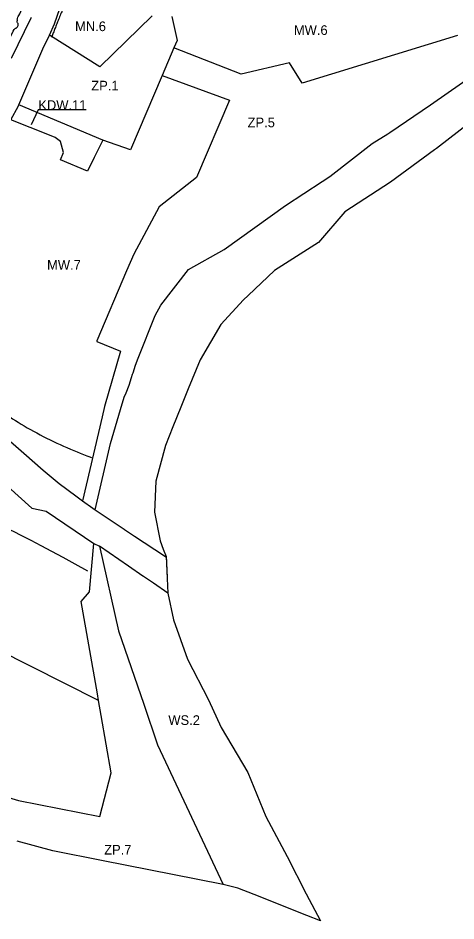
# Model space of a CAD drawing. Extents: x 7424788 to 7425732, y 5549810 to 5550591.
# Drawn here: x 7425235.6 to 7425416.8, y 5549810.3 to 5550184.4 of the extents above; entities that cross this region are included whole.
import ezdxf

# ---------------------------------------------------------------- set-up
doc = ezdxf.new("R2010")
doc.units = 0
for name, color, linetype in [('WIL_granica obszaru objętego planem', 7, 'Continuous'), ('WIL_linia rozgraniczające tereny o różnym przeznaczeniu lub różnych zasadach zagospodarowania', 7, 'Continuous'), ('WIL_linia rozgraniczające tereny o różnym przeznaczeniu lub różnych zasadach zagospodarowania_OPISY', 7, 'Continuous'), ('WIL_nieprzekraczalne linie zabudowy', 7, 'Continuous')]:
    doc.layers.add(name, color=color, linetype=linetype)

msp = doc.modelspace()

# ---------------------------------------------------------------- linework, layer by layer
at = {"layer": 'WIL_granica obszaru objętego planem'}
for p, q in [((7425407.96, 5550129.83), (7425389.71, 5550116.43)), ((7425360, 5550091.47), (7425341.78, 5550079.86)), ((7425341.78, 5550079.86), (7425330.79, 5550069.41)), ((7425294.44, 5549967.79), (7425295.65, 5549964.3)), ((7425295.65, 5549964.3), (7425296.91, 5549961.35)), ((7425296.91, 5549961.35), (7425297.65, 5549946.19)), ((7425319.68, 5549890.47), (7425330.71, 5549871.85)), ((7425330.71, 5549871.85), (7425338.21, 5549853.65)), ((7425338.21, 5549853.65), (7425346.99, 5549836.99)), ((7425346.99, 5549836.99), (7425354.82, 5549821.59)), ((7425326.6, 5549823.95), (7425320.44, 5549825.47)), ((7425333.35, 5549821.26), (7425326.6, 5549823.95)), ((7425354.82, 5549821.59), (7425360.83, 5549810.31))]:
    msp.add_line(p, q, dxfattribs=at)
for points in [[(7425440.98, 5550153.66), (7425422.93, 5550141.34), (7425408.74, 5550130.43), (7425407.96, 5550129.83)], [(7425389.71, 5550116.43), (7425370.86, 5550104.18), (7425360, 5550091.47)], [(7425330.79, 5550069.41), (7425328.9, 5550067.62), (7425319.6, 5550057.42)], [(7425319.6, 5550057.42), (7425310.98, 5550042.77), (7425306, 5550030.84), (7425303, 5550023.25), (7425299.7, 5550015.03)], [(7425299.7, 5550015.03), (7425296.62, 5550007.38), (7425292.61, 5549992.55)], [(7425292.61, 5549992.55), (7425292.14, 5549979.67), (7425294.44, 5549967.79)], [(7425297.65, 5549946.19), (7425299.98, 5549935.11), (7425305.76, 5549918.78), (7425314.39, 5549901.91), (7425319.68, 5549890.47)], [(7425270.8, 5549835.23), (7425250.01, 5549839.34), (7425235.24, 5549843.32)], [(7425320.44, 5549825.47), (7425299.52, 5549829.56), (7425270.8, 5549835.23)], [(7425360.83, 5549810.31), (7425355.08, 5549812.58), (7425333.35, 5549821.26)]]:
    msp.add_lwpolyline(points, dxfattribs=at)
msp.add_open_spline([(7425296.93, 5549961.04), (7425297.39, 5549951.5)], degree=1, dxfattribs=at)
at = {"layer": 'WIL_linia rozgraniczające tereny o różnym przeznaczeniu lub różnych zasadach zagospodarowania'}
for p, q in [((7425250.74, 5550182.05), (7425252.87, 5550188.4)), ((7425240.93, 5550184.38), (7425232.72, 5550167.74)), ((7425241.1, 5550184.72), (7425240.93, 5550184.38)), ((7425291.09, 5550185.38), (7425269.43, 5550164.2)), ((7425299.29, 5550185.06), (7425301.41, 5550175.18)), ((7425248.65, 5550177.3), (7425250.74, 5550182.05)), ((7425247.98, 5550175.79), (7425248.65, 5550177.3)), ((7425249.1, 5550177.02), (7425248.65, 5550177.3)), ((7425269.43, 5550164.2), (7425249.1, 5550177.02)), ((7425417.42, 5550177.24), (7425353.21, 5550157.39)), ((7425245.81, 5550171.63), (7425247.21, 5550174.53)), ((7425247.21, 5550174.53), (7425247.98, 5550175.79)), ((7425301.41, 5550175.18), (7425300.08, 5550172.04)), ((7425243.33, 5550165.86), (7425245.81, 5550171.63)), ((7425300.08, 5550172.04), (7425295.22, 5550160.57)), ((7425327.95, 5550161.15), (7425300.08, 5550172.04)), ((7425235.89, 5550148.41), (7425243.33, 5550165.86)), ((7425347.9, 5550165.87), (7425327.95, 5550161.15)), ((7425353.21, 5550157.39), (7425347.9, 5550165.87)), ((7425406.34, 5550148.48), (7425432.46, 5550166.86)), ((7425295.22, 5550160.57), (7425282.2, 5550129.85)), ((7425295.22, 5550160.57), (7425323.19, 5550150.46)), ((7425323.19, 5550150.46), (7425309.45, 5550118.4)), ((7425232.57, 5550142.3), (7425235.74, 5550148.06)), ((7425235.74, 5550148.06), (7425235.89, 5550148.41)), ((7425270.67, 5550133.81), (7425235.89, 5550148.41)), ((7425389.52, 5550137.03), (7425406.34, 5550148.48)), ((7425248.67, 5550135.84), (7425232.57, 5550142.3)), ((7425250.95, 5550134.92), (7425248.67, 5550135.84)), ((7425382.11, 5550132.42), (7425388.64, 5550136.46)), ((7425388.64, 5550136.46), (7425389.52, 5550137.03)), ((7425253.18, 5550133.33), (7425250.95, 5550134.92)), ((7425254.45, 5550128.72), (7425253.18, 5550133.33)), ((7425270.67, 5550133.81), (7425267.16, 5550126.7)), ((7425282.2, 5550129.85), (7425270.67, 5550133.81)), ((7425364.7, 5550118.79), (7425382.11, 5550132.42)), ((7425253.18, 5550125.7), (7425254.45, 5550128.72)), ((7425407.96, 5550129.83), (7425389.71, 5550116.43)), ((7425264.31, 5550120.93), (7425253.18, 5550125.7)), ((7425267.16, 5550126.7), (7425264.31, 5550120.93)), ((7425309.45, 5550118.4), (7425294.07, 5550106.21)), ((7425346.27, 5550106.71), (7425361.44, 5550116.75)), ((7425361.44, 5550116.75), (7425364.7, 5550118.79)), ((7425294.07, 5550106.21), (7425283.46, 5550086.58)), ((7425320.95, 5550088.57), (7425346.27, 5550106.71)), ((7425360, 5550091.47), (7425341.78, 5550079.86)), ((7425306.1, 5550080.19), (7425320.95, 5550088.57)), ((7425283.46, 5550086.58), (7425280.53, 5550079.67)), ((7425280.53, 5550079.67), (7425268.2, 5550050.62)), ((7425294.74, 5550065.5), (7425306.1, 5550080.19)), ((7425341.78, 5550079.86), (7425330.79, 5550069.41)), ((7425292.35, 5550061.18), (7425294.74, 5550065.5)), ((7425285.33, 5550043.54), (7425292.35, 5550061.18)), ((7425268.2, 5550050.62), (7425268.27, 5550050.36)), ((7425268.27, 5550050.36), (7425278, 5550046.47)), ((7425278, 5550046.47), (7425271.32, 5550023.54)), ((7425284.16, 5550040.6), (7425285.33, 5550043.54)), ((7425283.2, 5550037.43), (7425284.16, 5550040.6)), ((7425281.66, 5550032.37), (7425282.61, 5550035.5)), ((7425282.61, 5550035.5), (7425283.03, 5550036.94)), ((7425283.03, 5550036.94), (7425283.2, 5550037.43)), ((7425280.3, 5550029.13), (7425281.66, 5550032.37)), ((7425278.01, 5550022.23), (7425279.54, 5550027.4)), ((7425279.54, 5550027.4), (7425280.3, 5550029.13)), ((7425271.32, 5550023.54), (7425270.43, 5550019.19)), ((7425273.87, 5550008.16), (7425278.01, 5550022.23)), ((7425270.43, 5550019.19), (7425262.31, 5549984.45)), ((7425231.35, 5550009.93), (7425238.05, 5550004.15)), ((7425267.57, 5549980.71), (7425273.87, 5550008.16)), ((7425216.3, 5550003.77), (7425241.29, 5549981.33)), ((7425238.05, 5550004.15), (7425246.02, 5549997.14)), ((7425246.02, 5549997.14), (7425252.63, 5549991.58)), ((7425252.63, 5549991.58), (7425259.51, 5549986.44)), ((7425259.51, 5549986.44), (7425262.31, 5549984.45)), ((7425262.31, 5549984.45), (7425266.58, 5549981.41)), ((7425241.29, 5549981.33), (7425247.29, 5549980.06)), ((7425247.29, 5549980.06), (7425266.97, 5549966.64)), ((7425266.58, 5549981.41), (7425267.57, 5549980.71)), ((7425267.57, 5549980.71), (7425279.52, 5549972.59)), ((7425279.52, 5549972.59), (7425279.66, 5549972.5)), ((7425279.66, 5549972.5), (7425283.81, 5549969.76)), ((7425283.81, 5549969.76), (7425296.24, 5549961.55)), ((7425294.44, 5549967.79), (7425295.65, 5549964.3)), ((7425265.15, 5549946.68), (7425266.97, 5549966.64)), ((7425266.97, 5549966.64), (7425269.31, 5549965.64)), ((7425269.31, 5549965.64), (7425277.22, 5549930.55)), ((7425281.27, 5549957.34), (7425269.31, 5549965.64)), ((7425295.65, 5549964.3), (7425296.91, 5549961.35)), ((7425296.24, 5549961.55), (7425296.92, 5549961.07)), ((7425296.91, 5549961.35), (7425296.92, 5549961.07)), ((7425296.91, 5549961.35), (7425297.65, 5549946.19)), ((7425287.25, 5549953.19), (7425281.27, 5549957.34)), ((7425287.54, 5549953), (7425287.25, 5549953.19)), ((7425291.65, 5549950.24), (7425287.54, 5549953)), ((7425297.65, 5549946.19), (7425291.65, 5549950.24)), ((7425261.76, 5549942.7), (7425265.15, 5549946.68)), ((7425268.43, 5549904.42), (7425261.76, 5549942.7)), ((7425268.92, 5549901.61), (7425201.1, 5549935.93)), ((7425277.22, 5549930.55), (7425287.6, 5549900.15)), ((7425268.92, 5549901.61), (7425268.43, 5549904.42)), ((7425269.99, 5549895.47), (7425268.92, 5549901.61)), ((7425287.6, 5549900.15), (7425293.34, 5549883.35)), ((7425274.16, 5549871.63), (7425269.99, 5549895.47)), ((7425319.68, 5549890.47), (7425330.71, 5549871.85)), ((7425293.34, 5549883.35), (7425320.44, 5549825.47)), ((7425269.51, 5549853.6), (7425274.16, 5549871.63)), ((7425330.71, 5549871.85), (7425338.21, 5549853.65)), ((7425209.88, 5549868.2), (7425235.83, 5549860.15)), ((7425235.83, 5549860.15), (7425269.51, 5549853.6)), ((7425338.21, 5549853.65), (7425346.99, 5549836.99)), ((7425346.99, 5549836.99), (7425354.82, 5549821.59)), ((7425326.6, 5549823.95), (7425320.44, 5549825.47)), ((7425333.35, 5549821.26), (7425326.6, 5549823.95)), ((7425354.82, 5549821.59), (7425360.83, 5549810.31))]:
    msp.add_line(p, q, dxfattribs=at)
for points in [[(7425440.98, 5550153.66), (7425422.93, 5550141.34), (7425408.74, 5550130.43), (7425407.96, 5550129.83)], [(7425389.71, 5550116.43), (7425370.86, 5550104.18), (7425360, 5550091.47)], [(7425330.79, 5550069.41), (7425328.9, 5550067.62), (7425319.6, 5550057.42)], [(7425319.6, 5550057.42), (7425310.98, 5550042.77), (7425306, 5550030.84), (7425303, 5550023.25), (7425299.7, 5550015.03)], [(7425299.7, 5550015.03), (7425296.62, 5550007.38), (7425292.61, 5549992.55)], [(7425292.61, 5549992.55), (7425292.14, 5549979.67), (7425294.44, 5549967.79)], [(7425297.65, 5549946.19), (7425299.98, 5549935.11), (7425305.76, 5549918.78), (7425314.39, 5549901.91), (7425319.68, 5549890.47)], [(7425270.8, 5549835.23), (7425250.01, 5549839.34), (7425235.24, 5549843.32)], [(7425320.44, 5549825.47), (7425299.52, 5549829.56), (7425270.8, 5549835.23)], [(7425360.83, 5549810.31), (7425355.08, 5549812.58), (7425333.35, 5549821.26)]]:
    msp.add_lwpolyline(points, dxfattribs=at)
at = {"layer": 'WIL_linia rozgraniczające tereny o różnym przeznaczeniu lub różnych zasadach zagospodarowania_OPISY'}
msp.add_lwpolyline([(7425263.78, 5550146.38), (7425244, 5550146.38), (7425241.05, 5550140.2)], dxfattribs=at)
at = {"layer": 'WIL_nieprzekraczalne linie zabudowy'}
for points, degree in [([(7425260.39, 5550202.49), (7425252.71, 5550185.44), (7425249.46, 5550176.31)], 2), ([(7425229.43, 5550170.39), (7425234.03, 5550180.16), (7425234.68, 5550180.2), (7425234.98, 5550180.28), (7425235.75, 5550181.41), (7425235.7, 5550182.14), (7425235, 5550182.73), (7425235.55, 5550183.56), (7425234.96, 5550184.24), (7425236.88, 5550186.76), (7425240.12, 5550196.02)], 3), ([(7425197.48, 5550049.33), (7425201.22, 5550045.72), (7425214.43, 5550033.52), (7425224.47, 5550023.95), (7425243.95, 5550011.41), (7425259.92, 5550004.53), (7425266.6, 5550002.11)], 3), ([(7425264.48, 5549955.27), (7425206.42, 5549987.57), (7425200.28, 5549980.12), (7425180.2, 5549956.9), (7425165.28, 5549939.53)], 3)]:
    msp.add_open_spline(points, degree=degree, dxfattribs=at)

# ---------------------------------------------------------------- texts
at = {"layer": 'WIL_linia rozgraniczające tereny o różnym przeznaczeniu lub różnych zasadach zagospodarowania_OPISY'}
for s, p in [('MN.6', (7425259.21, 5550179.02)), ('MW.6', (7425349.78, 5550177.45)), ('ZP.1', (7425265.92, 5550154.43)), ('KDW.11', (7425244, 5550146.38)), ('ZP.5', (7425330.62, 5550139.17)), ('MW.7', (7425247.62, 5550080.14)), ('WS.2', (7425297.81, 5549891.53)), ('ZP.7', (7425271.25, 5549837.82))]:
    msp.add_text(s, height=4, dxfattribs=at).set_placement(p)

doc.saveas('drawing.dxf')
